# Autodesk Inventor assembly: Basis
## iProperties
Shininess: 64.0
Length Units: 11269
Angle Units: 11279
Time Units: 11290
Mass Units: 11283
Length Display Precision: 3
Angle Display Precision: 2
Compacted: True
Created: 2004-10
Part Number: Basis
Document SubType Name: Assembly
Designer: W. Holzwarth
Manufacturer: Standard
Standards Organization: Custom
Density: 0.0
Volumn: 0.0
Area: 0.0
PropertySet Name: Model Information
Control State: 0
Master: False
Checked Out: False
Author: W. Holzwarth
